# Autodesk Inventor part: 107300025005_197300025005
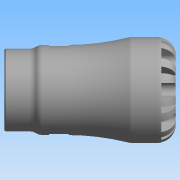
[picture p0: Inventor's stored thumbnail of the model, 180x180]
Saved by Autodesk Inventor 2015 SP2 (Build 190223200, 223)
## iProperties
Created: 2016-12
Part Number: 107300025005_197300025005
Material: Generic
Description: PLASSON FEMALE INTEGRAL BRASS THREAD 25X1/2" SERIES 1
Document SubType Name: Modeling
Designer: KIM
Density: 1 g/cm^3
Appearance: Default
Author: KIM
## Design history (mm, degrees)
derived "1073.ipt"
feature "Solid1::1073.ipt"
tag "TaggingFeature1"
body "Solid1"
other parameters: "d0" = 76, "d1" = 20.16, "d2" = 25, "d3" = 31.25, "d4" = 47, "d6" = 48, "d8" = 39.95, "d13" = 6.3, "d14" = 6.3, "d15" = 0, "d17" = 360 deg, "d19" = 8 deg, "d20" = 0.5, "d21" = 0.5, "d22" = 8 deg, "d24" = 0, "d26" = 360 deg, "d32" = 4.7, "d33" = 4.7, "d39" = 0.55893, "d42" = 18.631, "d43" = 36.66, "d46" = 2.08333, "d47" = 15, "d48" = 17.69945, "d50" = 4.29, "d51" = 0.47, "d54" = 8.75, "d55" = 5.5, "d57" = 12.348, "d58" = 0, "d68" = 360 deg, "d72" = 0.5, "d74" = 0, "d76" = 7.4375, "d_" = 25, "E_" = 47, "H_" = 76, "l_" = 48, "G_" = 18.631, "l_2" = 15, "d9" = 7.875, "d11" = 47, "d12" = 31.25, "d49" = 13
